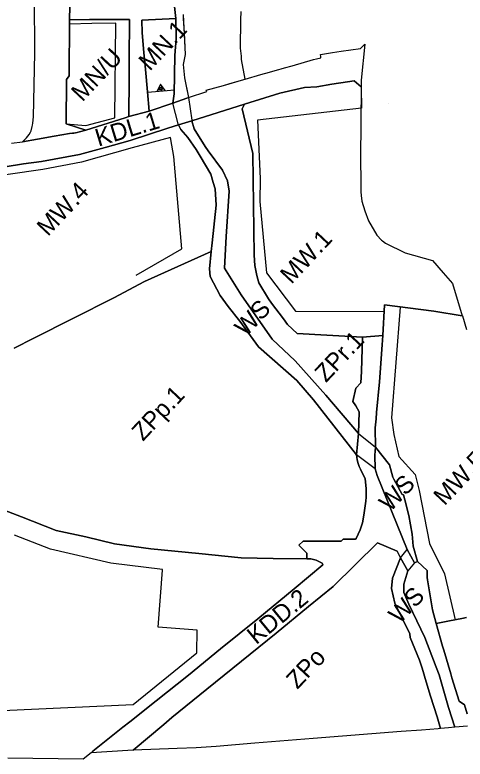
# Model space of a CAD drawing. Extents: x 7425782 to 7428854, y 5550411 to 5553074.
# Drawn here: x 7425945.6 to 7426175.7, y 5550411.4 to 5550791.4 of the extents above; entities that cross this region are included whole.
import ezdxf

# ---------------------------------------------------------------- set-up
doc = ezdxf.new("R2010")
doc.units = 0
for name, color, linetype in [('LIN_Linie rozgraniczajace WS', 7, 'Continuous'), ('LIN_linie_rozgraniczajace', 7, 'Continuous'), ('LIN_nieprzekraczalna linia zabudowy', 7, 'Continuous'), ('tereny MPZP_PRADNIK_CZERWONY_NACZELNA', 7, 'Continuous'), ('TXT_oznaczenia przeznaczen', 7, 'Continuous')]:
    doc.layers.add(name, color=color, linetype=linetype)

msp = doc.modelspace()

# ---------------------------------------------------------------- linework, layer by layer
at = {"layer": 'LIN_Linie rozgraniczajace WS'}
msp.add_line((7426121.16, 5550577.62), (7426129.93, 5550570.66), dxfattribs=at)
for points in [[(7426029.28, 5550735.33), (7426029.03, 5550735.84), (7426026.42, 5550746.3)], [(7426034.37, 5550749.29), (7426035.99, 5550737.65), (7426036.06, 5550737.4)], [(7426129.75, 5550559.71), (7426120.17, 5550566.71)], [(7426142.72, 5550514.16), (7426146.04, 5550518.45)], [(7426149.83, 5550511.59), (7426146.37, 5550507.58)]]:
    msp.add_lwpolyline(points, dxfattribs=at)
at = {"layer": 'LIN_linie_rozgraniczajace'}
for points in [[(7425974.01, 5550809.64), (7425973.52, 5550788.95), (7425973.43, 5550760.3), (7425971.93, 5550758.49), (7425971.86, 5550735.8), (7425981.87, 5550732.57), (7425978.59, 5550731.67), (7425977.45, 5550731.42), (7425975.74, 5550731.08), (7425975.13, 5550731.03), (7425973.52, 5550730.8), (7425965.68, 5550729.46), (7425957.16, 5550727.9), (7425949.57, 5550726.63), (7425949.57, 5550726.63), (7425950.87, 5550727.93), (7425951.58, 5550728.64), (7425953.01, 5550730.44), (7425953.01, 5550730.44), (7425953.58, 5550731.58), (7425953.92, 5550732.28), (7425953.92, 5550732.28), (7425954.51, 5550734.49), (7425954.63, 5550735.2), (7425954.8, 5550736.17), (7425955.13, 5550739.35), (7425955.84, 5550771.93), (7425955.61, 5550800.27)], [(7426026.76, 5550800.54), (7426027.84, 5550789.67), (7426010.47, 5550788.66), (7426010.65, 5550782.25), (7426011.51, 5550772.25), (7426012.3, 5550763.56), (7426013.33, 5550752.08), (7426014.32, 5550742.24), (7426003.83, 5550739.53), (7426003.85, 5550743.08), (7426004.04, 5550755.55), (7426004.08, 5550768.68), (7426004.13, 5550789.16), (7426001.36, 5550789.16), (7425999.95, 5550789.15), (7425983.83, 5550789.05), (7425973.52, 5550788.95), (7425974.01, 5550809.64)], [(7426031.6, 5550791.55), (7426031.62, 5550791.15), (7426031.69, 5550789.63), (7426032.06, 5550782.24), (7426032.6, 5550771.29), (7426032.6, 5550771.29), (7426032.43, 5550770.44), (7426031.56, 5550766.17), (7426031.56, 5550766.17), (7426032.26, 5550759.31), (7426033.17, 5550755.01), (7426034.37, 5550749.29), (7426034.37, 5550749.29), (7426033.44, 5550748.97), (7426026.42, 5550746.3), (7426027.01, 5550751.12), (7426027.35, 5550770.63), (7426028.11, 5550779.34), (7426027.84, 5550789.67), (7426026.76, 5550800.54)], [(7425943.9, 5550725.91), (7425949.57, 5550726.63), (7425949.57, 5550726.63), (7425957.16, 5550727.9), (7425965.68, 5550729.46), (7425973.52, 5550730.8), (7425975.13, 5550731.03), (7425975.74, 5550731.08), (7425977.45, 5550731.42), (7425978.59, 5550731.67), (7425981.87, 5550732.57), (7426002, 5550738.94), (7426003.83, 5550739.53), (7426014.32, 5550742.24), (7426026.42, 5550746.3), (7426033.44, 5550748.97), (7426034.37, 5550749.29), (7426034.37, 5550749.29), (7426043.65, 5550752.36), (7426043.37, 5550753), (7426052.25, 5550755.36), (7426055.51, 5550756.33), (7426063.21, 5550758.64), (7426071.34, 5550760.93), (7426075.79, 5550762.18), (7426079.82, 5550763.34), (7426080.53, 5550763.54), (7426081.63, 5550763.85), (7426083.43, 5550764.37), (7426087.38, 5550765.5), (7426098.23, 5550768.6), (7426099.72, 5550768.99), (7426102.02, 5550769.58), (7426101.92, 5550770.26), (7426101.77, 5550771.26), (7426101.77, 5550771.26), (7426107.98, 5550772.2), (7426112.41, 5550772.87), (7426122.25, 5550774.32), (7426124.37, 5550776.44), (7426124.42, 5550776.49), (7426122.53, 5550758.15), (7426122.5, 5550754.65), (7426122.5, 5550754.65), (7426119.07, 5550757.71), (7426115.54, 5550757.27), (7426107.58, 5550756.05), (7426099.86, 5550754.69), (7426093.65, 5550754.4), (7426081.07, 5550751.42), (7426063.03, 5550745.8), (7426036.06, 5550737.4), (7426029.28, 5550735.33), (7426023.77, 5550733.66), (7426004.47, 5550727.3), (7425991.68, 5550723.75), (7425978.69, 5550720.12), (7425959.27, 5550716.49), (7425950.06, 5550715.41), (7425922.75, 5550711.03)], [(7425922.75, 5550711.03), (7425950.06, 5550715.41), (7425959.27, 5550716.49), (7425978.69, 5550720.12), (7425991.68, 5550723.75), (7426004.47, 5550727.3), (7426023.77, 5550733.66), (7426029.28, 5550735.33), (7426030.44, 5550732.96), (7426033.95, 5550728.9), (7426038.24, 5550722.65), (7426040.26, 5550719.31), (7426045.83, 5550710.13), (7426046.97, 5550705.8), (7426048.02, 5550702.68), (7426048.41, 5550694.3), (7426046.39, 5550675.06), (7426045.94, 5550670.55), (7426011.84, 5550655.32), (7425996.17, 5550646.93), (7425975.27, 5550636.46), (7425955.3, 5550626.36), (7425945.26, 5550621.27)], [(7425945.26, 5550621.27), (7425955.3, 5550626.36), (7425975.27, 5550636.46), (7425996.17, 5550646.93), (7426011.84, 5550655.32), (7426045.94, 5550670.55), (7426045.03, 5550661.7), (7426045.41, 5550657.8), (7426050.58, 5550648.18), (7426054.57, 5550642.5), (7426060.5, 5550635.03), (7426070.16, 5550621.89), (7426089.62, 5550604.77), (7426098.27, 5550594.93), (7426120.17, 5550566.71), (7426120.27, 5550565.65), (7426120.52, 5550564.25), (7426121.03, 5550562.28), (7426121.59, 5550560.77), (7426122.14, 5550559.49), (7426124.67, 5550554.47), (7426125.05, 5550549.56), (7426125.07, 5550545.09), (7426124.88, 5550543.14), (7426124.28, 5550538.4), (7426123.97, 5550535.99), (7426123.2, 5550531.99), (7426122.04, 5550528.56), (7426120.03, 5550524.01), (7426119.94, 5550523.83), (7426119.72, 5550523.7), (7426113.68, 5550523.67), (7426113.39, 5550523.68), (7426112.41, 5550522.7), (7426092.9, 5550522.75), (7426090.77, 5550520.63), (7426094.84, 5550516.54), (7426094.83, 5550513.74), (7426077.62, 5550513.8), (7426061.19, 5550514.27), (7426039.68, 5550516.39), (7426015.17, 5550518.82), (7425996.53, 5550521.32), (7425981.85, 5550524.83), (7425966.76, 5550528.16), (7425949.04, 5550535.13), (7425933.38, 5550541)], [(7426176.31, 5550483.75), (7426173.99, 5550483.27), (7426167.7, 5550481.94), (7426160.86, 5550480.65), (7426159.05, 5550487.6), (7426156.5, 5550502.97), (7426156.24, 5550504.11), (7426156.33, 5550507.7), (7426151.38, 5550512.28), (7426149.11, 5550520.17), (7426148.65, 5550526.21), (7426146.87, 5550535.82), (7426144.92, 5550543.85), (7426144.21, 5550546.41), (7426143.47, 5550546.59), (7426139.31, 5550554.38), (7426138.68, 5550555.45), (7426137.11, 5550561.68), (7426129.93, 5550570.66), (7426129.67, 5550580.58), (7426130.15, 5550585.14), (7426130.42, 5550588.39), (7426131.95, 5550604.06), (7426133.35, 5550623), (7426133.7, 5550627.67), (7426134.57, 5550643.45), (7426159.77, 5550640.14), (7426174.25, 5550637.77), (7426174.25, 5550637.76), (7426174.26, 5550637.76), (7426176.4, 5550630.72)], [(7426176.82, 5550428.25), (7426170.44, 5550427.64), (7426167.2, 5550437.72), (7426162.37, 5550454.52), (7426160.95, 5550458.35), (7426155.01, 5550473.59), (7426146.84, 5550490.53), (7426144.29, 5550496.54), (7426144.29, 5550500.73), (7426146.37, 5550507.58), (7426142.72, 5550514.16), (7426141, 5550517.66), (7426130.95, 5550521.81), (7426108.24, 5550499.48), (7426095.71, 5550489.37), (7426079.09, 5550475.73), (7426061.42, 5550461.43), (7426043.79, 5550447.11), (7426025.87, 5550432.62), (7426021.79, 5550429.16), (7426006.05, 5550416), (7426006.05, 5550416), (7425992.61, 5550415.17), (7425984.56, 5550414.68), (7425985.43, 5550415.38), (7426000.84, 5550427.77), (7426004.32, 5550430.5), (7426017.74, 5550441.12), (7426034.31, 5550454.35), (7426050.66, 5550467.66), (7426069.69, 5550482.99), (7426088.33, 5550498.28), (7426103, 5550510.54), (7426102.71, 5550511.54), (7426099.55, 5550512.93), (7426096.93, 5550513.73), (7426094.83, 5550513.74), (7426094.84, 5550516.54), (7426090.77, 5550520.63), (7426092.9, 5550522.75), (7426112.41, 5550522.7), (7426113.39, 5550523.68), (7426113.68, 5550523.67), (7426119.72, 5550523.7), (7426119.94, 5550523.83), (7426120.03, 5550524.01), (7426122.04, 5550528.56), (7426123.2, 5550531.99), (7426123.97, 5550535.99), (7426124.28, 5550538.4), (7426124.88, 5550543.14), (7426125.07, 5550545.09), (7426125.05, 5550549.56), (7426124.67, 5550554.47), (7426122.14, 5550559.49), (7426121.59, 5550560.77), (7426121.03, 5550562.28), (7426120.52, 5550564.25), (7426120.27, 5550565.65), (7426120.17, 5550566.71), (7426121.16, 5550577.62), (7426121.62, 5550588.78), (7426119.76, 5550591.78), (7426118.33, 5550594.08), (7426119.85, 5550600.77), (7426122.38, 5550603.47), (7426122.69, 5550609.29), (7426123.17, 5550626.9), (7426133.7, 5550627.67), (7426133.35, 5550623), (7426131.95, 5550604.06), (7426130.42, 5550588.39), (7426130.15, 5550585.14), (7426129.67, 5550580.58), (7426129.93, 5550570.66), (7426129.51, 5550566.59), (7426129.75, 5550559.71), (7426130.69, 5550556.26), (7426146.04, 5550518.45), (7426149.83, 5550511.59), (7426151.38, 5550512.28), (7426156.33, 5550507.7), (7426156.24, 5550504.11), (7426156.5, 5550502.97), (7426159.05, 5550487.6), (7426160.86, 5550480.65), (7426164.2, 5550469.13), (7426164.84, 5550467.08), (7426168.3, 5550455.02), (7426168.95, 5550452.91), (7426172.64, 5550441.04), (7426175.28, 5550439.16), (7426176.8, 5550434.46)], [(7425933.38, 5550541), (7425949.04, 5550535.13), (7425966.76, 5550528.16), (7425981.85, 5550524.83), (7425996.53, 5550521.32), (7426015.17, 5550518.82), (7426039.68, 5550516.39), (7426061.19, 5550514.27), (7426077.62, 5550513.8), (7426094.83, 5550513.74), (7426096.93, 5550513.73), (7426099.55, 5550512.93), (7426102.71, 5550511.54), (7426103, 5550510.54), (7426088.33, 5550498.28), (7426069.69, 5550482.99), (7426050.66, 5550467.66), (7426034.31, 5550454.35), (7426017.74, 5550441.12), (7426004.32, 5550430.5), (7426000.84, 5550427.77), (7425985.43, 5550415.38), (7425984.56, 5550414.68), (7425984.56, 5550414.68), (7425980.47, 5550411.4), (7425942.1, 5550411.9)], [(7426176.8, 5550434.46), (7426175.28, 5550439.16), (7426172.64, 5550441.04), (7426168.95, 5550452.91), (7426168.3, 5550455.02), (7426164.84, 5550467.08), (7426164.2, 5550469.13), (7426160.86, 5550480.65), (7426167.7, 5550481.94), (7426173.99, 5550483.27), (7426176.31, 5550483.75)]]:
    msp.add_lwpolyline(points, dxfattribs=at)
for points in [[(7426003.83, 5550739.53), (7426002, 5550738.94), (7425981.87, 5550732.57), (7425971.86, 5550735.8), (7425971.93, 5550758.49), (7425973.43, 5550760.3), (7425973.52, 5550788.95), (7425983.83, 5550789.05), (7425999.95, 5550789.15), (7426001.36, 5550789.16), (7426004.13, 5550789.16), (7426004.08, 5550768.68), (7426004.04, 5550755.55), (7426003.85, 5550743.08)], [(7426026.42, 5550746.3), (7426014.32, 5550742.24), (7426013.33, 5550752.08), (7426012.3, 5550763.56), (7426011.51, 5550772.25), (7426010.65, 5550782.25), (7426010.47, 5550788.66), (7426027.84, 5550789.67), (7426028.11, 5550779.34), (7426027.35, 5550770.63), (7426027.01, 5550751.12)], [(7426169.23, 5550654.26), (7426174.25, 5550637.76), (7426174.25, 5550637.77), (7426159.77, 5550640.14), (7426134.57, 5550643.45), (7426133.7, 5550627.67), (7426123.17, 5550626.9), (7426089.88, 5550628.77), (7426084.96, 5550633.42), (7426082.92, 5550636.18), (7426076.73, 5550644.3), (7426075.15, 5550646.37), (7426070.23, 5550654.56), (7426069.17, 5550658.4), (7426068.29, 5550663.53), (7426067.95, 5550668.73), (7426067.16, 5550720.45), (7426067.13, 5550720.67), (7426061.77, 5550743.53), (7426063.03, 5550745.8), (7426081.07, 5550751.42), (7426093.65, 5550754.4), (7426099.86, 5550754.69), (7426107.58, 5550756.05), (7426115.54, 5550757.27), (7426119.07, 5550757.71), (7426122.5, 5550754.65), (7426122.5, 5550754.65), (7426122.26, 5550718.22), (7426122.38, 5550705.84), (7426122.42, 5550701.01), (7426122.61, 5550699.28), (7426122.95, 5550696.3), (7426124.39, 5550691.4), (7426126.36, 5550686.19), (7426130.55, 5550678.94), (7426133.03, 5550676.36), (7426133.03, 5550676.35), (7426133.03, 5550676.35), (7426133.49, 5550675.99), (7426134.92, 5550674.86), (7426145.09, 5550669.85), (7426159.05, 5550666.03), (7426164.45, 5550659.79)], [(7426123.17, 5550626.9), (7426122.69, 5550609.29), (7426122.38, 5550603.47), (7426119.85, 5550600.77), (7426118.33, 5550594.08), (7426119.76, 5550591.78), (7426121.62, 5550588.78), (7426121.16, 5550577.62), (7426104.48, 5550597.25), (7426088.78, 5550614.79), (7426077.16, 5550625.81), (7426061.33, 5550648.56), (7426052.65, 5550662.08), (7426053.51, 5550678.34), (7426055.18, 5550701.34), (7426054.22, 5550706.63), (7426051.73, 5550712.16), (7426044.34, 5550722.08), (7426042.78, 5550724.17), (7426037.2, 5550733.19), (7426036.06, 5550737.4), (7426063.03, 5550745.8), (7426061.77, 5550743.53), (7426067.13, 5550720.67), (7426067.16, 5550720.45), (7426067.95, 5550668.73), (7426068.29, 5550663.53), (7426069.17, 5550658.4), (7426070.23, 5550654.56), (7426075.15, 5550646.37), (7426076.73, 5550644.3), (7426082.92, 5550636.18), (7426084.96, 5550633.42), (7426089.88, 5550628.77)], [(7426121.16, 5550577.62), (7426120.17, 5550566.71), (7426098.27, 5550594.93), (7426089.62, 5550604.77), (7426070.16, 5550621.89), (7426060.5, 5550635.03), (7426054.57, 5550642.5), (7426050.58, 5550648.18), (7426045.41, 5550657.8), (7426045.03, 5550661.7), (7426045.94, 5550670.55), (7426046.39, 5550675.06), (7426048.41, 5550694.3), (7426048.02, 5550702.68), (7426046.97, 5550705.8), (7426045.83, 5550710.13), (7426040.26, 5550719.31), (7426038.24, 5550722.65), (7426033.95, 5550728.9), (7426030.44, 5550732.96), (7426029.28, 5550735.33), (7426036.06, 5550737.4), (7426037.2, 5550733.19), (7426042.78, 5550724.17), (7426044.34, 5550722.08), (7426051.73, 5550712.16), (7426054.22, 5550706.63), (7426055.18, 5550701.34), (7426053.51, 5550678.34), (7426052.65, 5550662.08), (7426061.33, 5550648.56), (7426077.16, 5550625.81), (7426088.78, 5550614.79), (7426104.48, 5550597.25)], [(7426151.38, 5550512.28), (7426149.83, 5550511.59), (7426146.04, 5550518.45), (7426130.69, 5550556.26), (7426129.75, 5550559.71), (7426129.51, 5550566.59), (7426129.93, 5550570.66), (7426137.11, 5550561.68), (7426138.68, 5550555.45), (7426139.31, 5550554.38), (7426143.47, 5550546.59), (7426144.21, 5550546.41), (7426144.92, 5550543.85), (7426146.87, 5550535.82), (7426148.65, 5550526.21), (7426149.11, 5550520.17)], [(7426028.6, 5550416.78), (7426006.05, 5550416), (7426006.05, 5550416), (7426021.79, 5550429.16), (7426025.87, 5550432.62), (7426043.79, 5550447.11), (7426061.42, 5550461.43), (7426079.09, 5550475.73), (7426095.71, 5550489.37), (7426108.24, 5550499.48), (7426130.95, 5550521.81), (7426141, 5550517.66), (7426142.72, 5550514.16), (7426138.59, 5550503.75), (7426138.04, 5550498.51), (7426139.79, 5550490.96), (7426147.45, 5550475.44), (7426147.55, 5550473.55), (7426152.43, 5550461.87), (7426153.77, 5550457.87), (7426155.71, 5550450.94), (7426158.02, 5550443.51), (7426161.41, 5550432.94), (7426163.12, 5550427.06), (7426161.86, 5550426.92), (7426153.38, 5550426.25), (7426143.02, 5550425.43), (7426127.97, 5550424.23), (7426098.06, 5550421.86), (7426068.15, 5550419.49), (7426048.49, 5550417.92), (7426038.26, 5550417.11)], [(7426170.44, 5550427.64), (7426167.22, 5550427.33), (7426163.12, 5550427.06), (7426161.41, 5550432.94), (7426158.02, 5550443.51), (7426155.71, 5550450.94), (7426153.77, 5550457.87), (7426152.43, 5550461.87), (7426147.55, 5550473.55), (7426147.45, 5550475.44), (7426139.79, 5550490.96), (7426138.04, 5550498.51), (7426138.59, 5550503.75), (7426142.72, 5550514.16), (7426146.37, 5550507.58), (7426144.29, 5550500.73), (7426144.29, 5550496.54), (7426146.84, 5550490.53), (7426155.01, 5550473.59), (7426160.95, 5550458.35), (7426162.37, 5550454.52), (7426167.2, 5550437.72)]]:
    msp.add_lwpolyline(points, close=True, dxfattribs=at)
at = {"layer": 'LIN_nieprzekraczalna linia zabudowy'}
msp.add_line((7426136.4, 5550745.95), (7426136.4, 5550745.95), dxfattribs=at)
for points in [[(7425996.68, 5550738.82), (7425997.21, 5550787.28), (7425984.98, 5550787.09), (7425973.51, 5550786.68)], [(7426028.01, 5550781.27), (7426028.01, 5550781.27)], [(7426122.5, 5550754.11), (7426122.73, 5550743.88), (7426069.64, 5550737.63)], [(7426013.33, 5550752.01), (7426023.49, 5550752.84), (7426027.05, 5550753.15)], [(7425971.86, 5550735.8), (7425981.88, 5550734.88), (7425996.68, 5550738.82)], [(7426069.64, 5550737.63), (7426070.89, 5550707.86), (7426070.82, 5550696.15), (7426074.15, 5550659.68), (7426088.98, 5550640.17), (7426134.38, 5550640.04)], [(7426025.85, 5550724.85), (7426025.1, 5550728.83), (7426005.63, 5550723.48), (7425979.6, 5550716.22), (7425959.87, 5550712.53), (7425925.59, 5550707.59)], [(7426030.97, 5550672.01), (7426026.9, 5550719.15), (7426025.85, 5550724.85)], [(7426007.68, 5550658.49), (7426030.97, 5550672.01)], [(7426142.42, 5550642.17), (7426138.02, 5550585.62), (7426139.2, 5550577.11), (7426141.79, 5550565.89), (7426150.09, 5550556.71), (7426152.21, 5550548.63), (7426157.54, 5550521.48), (7426165.16, 5550506.03), (7426170.59, 5550482.55)], [(7425939.3, 5550436.29), (7426006.01, 5550439.3), (7426038.57, 5550465.66), (7426038.8, 5550477.31), (7426018.79, 5550478.82), (7426021.07, 5550507.81), (7426021.1, 5550508.19), (7425994.7, 5550511.48), (7425963.83, 5550518.56), (7425945.46, 5550525.8)]]:
    msp.add_lwpolyline(points, dxfattribs=at)
msp.add_lwpolyline([(7426020.34, 5550752.59), (7426022.34, 5550752.76), (7426020.06, 5550756.05), (7426018.35, 5550752.43), (7426020.34, 5550752.59), (7426020.29, 5550753.29), (7426019.5, 5550753.23), (7426020.17, 5550754.65), (7426021.07, 5550753.36), (7426020.29, 5550753.29)], close=True, dxfattribs=at)
at = {"layer": 'tereny MPZP_PRADNIK_CZERWONY_NACZELNA'}
for p, q in [((7426061.16, 5550788.96), (7426061.21, 5550793.2)), ((7426060.9, 5550774.38), (7426061.16, 5550788.96))]:
    msp.add_line(p, q, dxfattribs=at)
for points in [[(7426031.6, 5550791.55), (7426032.6, 5550771.29), (7426031.56, 5550766.17), (7426032.26, 5550759.31), (7426034.37, 5550749.29), (7426043.65, 5550752.36), (7426043.37, 5550753), (7426052.25, 5550755.36), (7426062.64, 5550758.46), (7426063.21, 5550758.63)], [(7426063.21, 5550758.63), (7426061.46, 5550768.72), (7426061.4, 5550770.37), (7426060.9, 5550774.38)]]:
    msp.add_lwpolyline(points, dxfattribs=at)

# ---------------------------------------------------------------- texts
at = {"layer": 'TXT_oznaczenia przeznaczen'}
for s, rotation, p in [('MN.1', 46.7736, (7426014.56, 5550762.37)), ('MN/U', 46.7736, (7425980.09, 5550746.67)), ('KDL.1', 16.8333, (7425988.27, 5550724.12)), ('MW.4', 46.7736, (7425962.51, 5550677.93)), ('MW.1', 46.7736, (7426086.88, 5550653.57)), ('WS', 46.7736, (7426063.65, 5550626.63)), ('ZPr.1', 46.7967, (7426104.6, 5550603.35)), ('ZPp.1', 46.7736, (7426011.07, 5550573.41)), ('MW.5', 46.7736, (7426165.19, 5550540.41)), ('WS', 46.7736, (7426137.44, 5550537.26)), ('KDD.2', 39.4567, (7426068.91, 5550469.56)), ('WS', 46.7736, (7426142.28, 5550479.98)), ('ZPo', 46.7736, (7426089.96, 5550446.7))]:
    msp.add_text(s, height=9, rotation=rotation, dxfattribs=at).set_placement(p)

doc.saveas('drawing.dxf')
